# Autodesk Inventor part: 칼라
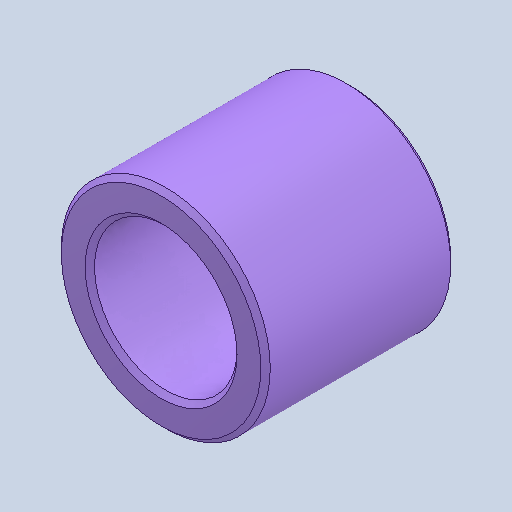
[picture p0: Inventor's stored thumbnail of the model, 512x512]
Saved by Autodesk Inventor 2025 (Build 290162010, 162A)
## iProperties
Created: 2024-07
Part Number: 칼라
Material: 스테인리스강
Document SubType Name: Modeling
Designer: Admin
Density: 8.08 g/cm^3
Appearance: 기본값
Author: jhkim
Sending System: Autodesk Inventor 2025
Preprocessor: ST-DEVELOPER v20
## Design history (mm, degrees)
feature "솔리드1"
node "솔리드2"
